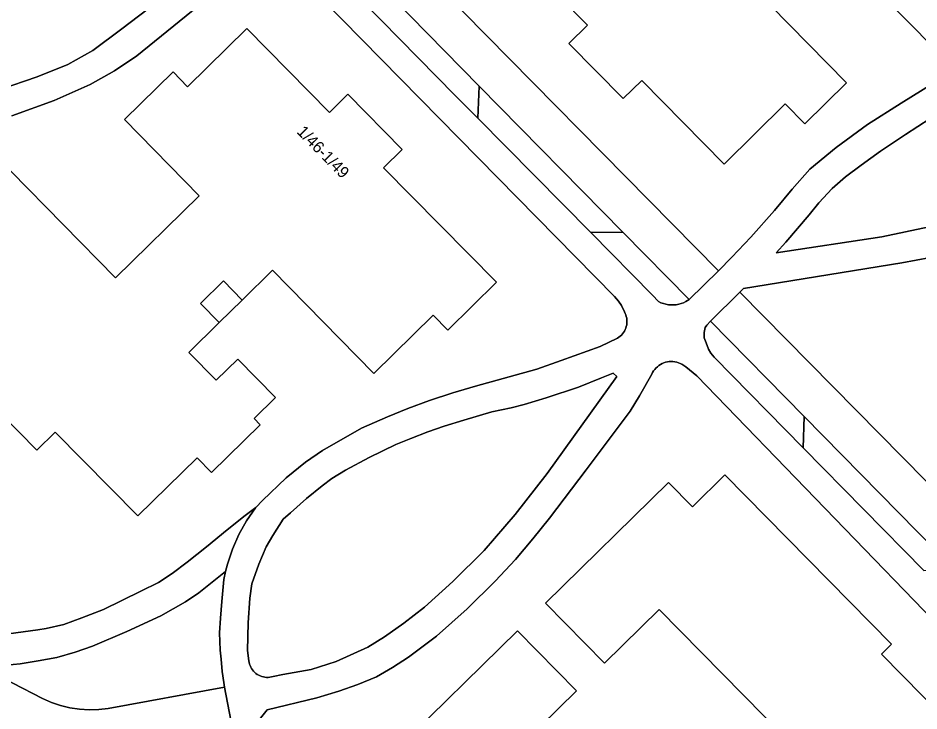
# Model space of a CAD drawing. Extents: x 162788 to 163838, y 385791 to 386523.
# Drawn here: x 162931.3 to 163008.9, y 386045.6 to 386105.3 of the extents above; entities that cross this region are included whole.
import ezdxf

# ---------------------------------------------------------------- set-up
doc = ezdxf.new("R2010")
doc.units = 0
for name, color, linetype in [('IMGEO_Berm_groen', 7, 'Continuous'), ('IMGEO_Erf', 7, 'Continuous'), ('IMGEO_Groenvoorziening', 7, 'Continuous'), ('IMGEO_Pand', 7, 'Continuous'), ('IMGEO_Pand_nummerreeks', 7, 'Continuous'), ('IMGEO_Pand_overbouw', 7, 'Continuous'), ('IMGEO_Parkeervlak_open', 7, 'Continuous'), ('IMGEO_Woonerf_gesloten', 7, 'Continuous'), ('IMGEO_Woonerf_open', 7, 'Continuous')]:
    doc.layers.add(name, color=color, linetype=linetype)

msp = doc.modelspace()

# ---------------------------------------------------------------- linework, layer by layer
at = {"layer": 'IMGEO_Berm_groen'}
for points in [[(162965.08, 386105.449), (162955.829, 386114.882), (162955.67, 386114.724), (162955.585, 386114.618), (162955.428, 386114.276), (162955.371, 386114.105), (162955.355, 386113.833), (162955.362, 386113.56), (162955.392, 386113.289), (162955.445, 386113.022), (162955.52, 386112.76), (162955.617, 386112.505), (162955.735, 386112.259), (162955.873, 386112.024), (162956.031, 386111.801), (162956.207, 386111.592), (162968.959, 386098.608), (162970.909, 386096.632), (162971.01, 386099.414)], [(162983.383, 386086.82), (162980.618, 386086.794), (162985.934, 386081.408), (162986.469, 386080.849), (162986.669, 386080.753), (162986.877, 386080.676), (162987.092, 386080.617), (162987.31, 386080.577), (162987.531, 386080.557), (162987.753, 386080.556), (162987.974, 386080.576), (162988.193, 386080.614), (162988.407, 386080.672), (162988.616, 386080.749), (162988.816, 386080.844), (162988.942, 386080.928), (162989.082, 386081.02)], [(162990.944, 386079.148), (162990.62, 386078.825), (162990.483, 386078.615), (162990.396, 386078.178), (162990.39, 386078.028), (162990.401, 386077.712), (162990.547, 386077.293), (162990.767, 386076.752), (162990.963, 386076.416), (162991.25, 386076.065), (162998.906, 386068.262), (162998.996, 386070.949)]]:
    msp.add_lwpolyline(points, close=True, dxfattribs=at)
at = {"layer": 'IMGEO_Erf'}
for points in [[(162996.056, 386106.378), (163002.631, 386099.689), (162999.051, 386096.17), (162997.375, 386097.874), (162992.098, 386092.687), (162985.007, 386099.902), (162983.413, 386098.336), (162978.742, 386103.088), (162980.335, 386104.654), (162970.65, 386114.508)], [(163015.416, 386107.909), (163010.138, 386102.721), (163001.39, 386111.622)], [(162926.041, 386051.625), (162933.013, 386052.569), (162933.742, 386052.696), (162935.247, 386053.046), (162936.802, 386053.624), (162938.661, 386054.329), (162941.895, 386055.895), (162943.405, 386056.649), (162944.576, 386057.437), (162945.884, 386058.394), (162947.555, 386059.728), (162949.331, 386061.183), (162950.86, 386062.423), (162951.804, 386063.106), (162952.362, 386063.711), (162954.399, 386065.67), (162956.061, 386067.017), (162957.518, 386068.011), (162960.88, 386069.936), (162963.125, 386070.93), (162964.884, 386071.639), (162966.754, 386072.319), (162968.761, 386072.976), (162970.713, 386073.558), (162975.991, 386075.021), (162978.07, 386075.777), (162981.439, 386076.986), (162982.931, 386077.699), (162983.051, 386077.779), (162983.163, 386077.868), (162983.267, 386077.967), (162983.362, 386078.074), (162983.448, 386078.189), (162983.524, 386078.31), (162983.589, 386078.438), (162983.643, 386078.571), (162983.685, 386078.708), (162983.716, 386078.848), (162983.734, 386078.99), (162983.74, 386079.133), (162983.734, 386079.276), (162983.716, 386079.419), (162983.686, 386079.559), (162983.644, 386079.696), (162983.59, 386079.829), (162983.525, 386079.956), (162983.265, 386080.523), (162983.02, 386080.87), (162982.66, 386081.282), (162954.193, 386110.271)], [(162965.639, 386109.891), (162991.633, 386083.508), (162992.764, 386084.687), (162994.399, 386086.394), (162996.434, 386088.681), (162997.975, 386090.519), (162999.497, 386092.25), (163001.748, 386094.127), (163004.452, 386096.104), (163007.355, 386097.946), (163010.914, 386100.137), (163014.526, 386102.37), (163018.012, 386104.467), (163019.81, 386105.476)], [(163034.593, 386105.372), (163032.927, 386102.387), (163031.643, 386100.544), (163030.645, 386099.338), (163027.569, 386096.044), (163022.475, 386091.076), (163020.687, 386089.641), (163019.2, 386088.539), (163019.01, 386088.395), (163017.057, 386087.161), (163014.761, 386086.098), (163012.296, 386085.312), (163009.878, 386084.654), (163007.401, 386084.184), (162993.768, 386081.986), (162993.461, 386081.653), (163039.475, 386034.95), (163041.516, 386037.028), (163076.704, 386072.029), (163076.476, 386072.907), (163056.429, 386093.317), (163049.21, 386100.56), (163041.713, 386107.825)], [(162947.311, 386106.699), (162941.55, 386102.006), (162939.629, 386100.72), (162937.541, 386099.543), (162934.439, 386098.157), (162930.777, 386096.853)], [(162930.69, 386092.088), (162939.722, 386082.898), (162946.911, 386089.964), (162940.472, 386096.515), (162944.659, 386100.63), (162945.913, 386099.353), (162951.013, 386104.365), (162958.121, 386097.133), (162959.715, 386098.699), (162964.386, 386093.946), (162962.793, 386092.38), (162972.495, 386082.509), (162968.309, 386078.394), (162967.054, 386079.671), (162961.955, 386074.659), (162953.224, 386083.541), (162950.621, 386080.983), (162948.997, 386082.635), (162947.014, 386080.687), (162948.638, 386079.034), (162948.614, 386079.011), (162946.035, 386076.475), (162948.385, 386074.084), (162950.23, 386075.897), (162953.491, 386072.58), (162951.647, 386070.766), (162952.172, 386070.232), (162947.986, 386066.117), (162946.731, 386067.393), (162941.632, 386062.381), (162934.523, 386069.614), (162932.93, 386068.048), (162928.259, 386072.8)], [(163011.849, 386051.6), (162989.767, 386074.455), (162988.809, 386075.231), (162988.47, 386075.446), (162988.326, 386075.52), (162988.176, 386075.581), (162988.022, 386075.628), (162987.864, 386075.662), (162987.703, 386075.682), (162987.541, 386075.687), (162987.38, 386075.678), (162987.22, 386075.655), (162987.062, 386075.618), (162986.909, 386075.568), (162986.76, 386075.504), (162986.618, 386075.427), (162986.483, 386075.338), (162986.356, 386075.237), (162986.239, 386075.126), (162986.132, 386075.005), (162986.035, 386074.875), (162985.951, 386074.736), (162985.88, 386074.591), (162984.829, 386072.717), (162984.021, 386071.401), (162980.229, 386066.357), (162977.078, 386062.205), (162975.634, 386060.423), (162974.149, 386058.622), (162972.405, 386056.76), (162969.989, 386054.397), (162967.345, 386052.021), (162964.947, 386050.227), (162963.558, 386049.32), (162962.181, 386048.538), (162960.58, 386047.87), (162958.929, 386047.281), (162957.046, 386046.716), (162952.772, 386045.677), (162952.201, 386044.966)], [(162997.379, 386043.276), (162986.518, 386054.326), (162981.811, 386049.699), (162976.729, 386054.87), (162987.312, 386065.272), (162989.376, 386063.173), (162992.179, 386065.928), (163006.528, 386051.329), (163005.665, 386050.481), (163011.004, 386045.049)], [(162963.728, 386042.091), (162974.311, 386052.493), (162979.393, 386047.323), (162974.686, 386042.696)]]:
    msp.add_lwpolyline(points, dxfattribs=at)
at = {"layer": 'IMGEO_Groenvoorziening'}
for points in [[(162929.787, 386099.112), (162932.958, 386100.213), (162935.592, 386101.258), (162937.761, 386102.46), (162940.24, 386104.343), (162943.236, 386106.606), (162946.028, 386108.902), (162949.063, 386111.524), (162950.921, 386113.462), (162948.954, 386115.694), (162947.799, 386116.794), (162946.824, 386117.743), (162946.592, 386117.975), (162939.45, 386114.029), (162938.78, 386111.247), (162928.686, 386105.678)], [(163009.853, 386096.622), (163007.712, 386095.24), (163005.571, 386093.816), (163003.901, 386092.61), (163002.561, 386091.584), (163001.4, 386090.589), (163000.259, 386089.362), (162999.427, 386088.32), (162997.429, 386085.958), (162996.591, 386085.049), (163005.677, 386086.422), (163009.76, 386087.281)], [(162928.277, 386049.302), (162933.436, 386046.663), (162934.194, 386046.325), (162934.979, 386046.056), (162935.786, 386045.858), (162936.606, 386045.733), (162937.435, 386045.682), (162938.265, 386045.705), (162939.089, 386045.802), (162949.104, 386047.652), (162949.031, 386048.049), (162948.89, 386048.985), (162948.796, 386050.058), (162948.72, 386050.827), (162948.671, 386052.304), (162948.757, 386053.581), (162948.852, 386055.03), (162949.026, 386056.922), (162949.185, 386057.594), (162946.884, 386055.763), (162945.735, 386054.981), (162943.62, 386053.772), (162940.69, 386052.427), (162937.717, 386051.164), (162936.23, 386050.641), (162934.657, 386050.182), (162933.055, 386049.899), (162931.506, 386049.649), (162929.659, 386049.476)]]:
    msp.add_lwpolyline(points, dxfattribs=at)
msp.add_lwpolyline([(162951.201, 386049.91), (162951.222, 386049.77), (162951.255, 386049.632), (162951.301, 386049.498), (162951.358, 386049.368), (162951.426, 386049.243), (162951.506, 386049.126), (162951.595, 386049.016), (162951.694, 386048.914), (162951.802, 386048.821), (162951.917, 386048.739), (162952.04, 386048.667), (162952.168, 386048.606), (162952.301, 386048.557), (162952.438, 386048.519), (162952.577, 386048.495), (162952.719, 386048.482), (162952.861, 386048.482), (162953.002, 386048.495), (162953.142, 386048.521), (162953.279, 386048.558), (162954.118, 386048.725), (162956.563, 386049.163), (162958.692, 386049.849), (162961.433, 386051.081), (162962.866, 386051.981), (162964.534, 386053.138), (162966.299, 386054.54), (162968.763, 386056.74), (162971.449, 386059.395), (162974.122, 386062.518), (162976.884, 386066.03), (162982.878, 386074.404), (162982.56, 386074.694), (162981.555, 386074.274), (162979.557, 386073.464), (162976.779, 386072.552), (162974.9, 386071.971), (162973.779, 386071.697), (162972.113, 386071.34), (162969.689, 386070.62), (162968, 386070.113), (162966.597, 386069.616), (162965.123, 386069.042), (162963.855, 386068.537), (162961.533, 386067.43), (162959.503, 386066.314), (162958.336, 386065.6), (162957.501, 386064.986), (162956.145, 386063.897), (162954.764, 386062.649), (162954.149, 386062.1), (162953.244, 386060.705), (162952.682, 386059.724), (162952.055, 386058.232), (162951.437, 386056.538), (162951.281, 386055.294), (162951.133, 386053.187), (162951.074, 386050.797)], close=True, dxfattribs=at)
at = {"layer": 'IMGEO_Pand'}
for points in [[(162970.65, 386114.508), (162980.335, 386104.654), (162978.742, 386103.088), (162983.413, 386098.336), (162985.007, 386099.902), (162992.098, 386092.687), (162997.375, 386097.874), (162999.051, 386096.17), (163002.631, 386099.689), (162996.056, 386106.378)], [(163001.39, 386111.622), (163010.138, 386102.721), (163015.416, 386107.909)], [(162928.259, 386072.8), (162932.93, 386068.048), (162934.523, 386069.614), (162941.632, 386062.381), (162946.731, 386067.393), (162947.986, 386066.117), (162952.172, 386070.232), (162951.647, 386070.766), (162953.491, 386072.58), (162950.23, 386075.897), (162948.385, 386074.084), (162946.035, 386076.475), (162948.614, 386079.011), (162948.638, 386079.034), (162947.014, 386080.687), (162948.997, 386082.635), (162950.621, 386080.983), (162953.224, 386083.541), (162961.955, 386074.659), (162967.054, 386079.671), (162968.309, 386078.394), (162972.495, 386082.509), (162962.793, 386092.38), (162964.386, 386093.946), (162959.715, 386098.699), (162958.121, 386097.133), (162951.013, 386104.365), (162945.913, 386099.353), (162944.659, 386100.63), (162940.472, 386096.515), (162946.911, 386089.964), (162939.722, 386082.898), (162930.69, 386092.088)], [(163011.004, 386045.049), (163005.665, 386050.481), (163006.528, 386051.329), (162992.179, 386065.928), (162989.376, 386063.173), (162987.312, 386065.272), (162976.729, 386054.87), (162981.811, 386049.699), (162986.518, 386054.326), (162997.379, 386043.276)], [(162974.686, 386042.696), (162979.393, 386047.323), (162974.311, 386052.493), (162963.728, 386042.091)]]:
    msp.add_lwpolyline(points, dxfattribs=at)
at = {"layer": 'IMGEO_Pand_overbouw'}
msp.add_lwpolyline([(162950.621, 386080.983), (162948.997, 386082.635), (162947.014, 386080.687), (162948.638, 386079.034)], close=True, dxfattribs=at)
at = {"layer": 'IMGEO_Parkeervlak_open'}
for points in [[(162971.01, 386099.414), (162970.909, 386096.632), (162980.618, 386086.794), (162983.383, 386086.82)], [(162998.996, 386070.949), (162998.906, 386068.262), (163009.288, 386057.681), (163011.984, 386057.726)]]:
    msp.add_lwpolyline(points, close=True, dxfattribs=at)
at = {"layer": 'IMGEO_Woonerf_gesloten'}
for points in [[(163010.914, 386100.137), (163007.355, 386097.946), (163004.452, 386096.104), (163001.748, 386094.127), (162999.497, 386092.25), (162997.975, 386090.519), (162996.434, 386088.681), (162994.399, 386086.394), (162992.764, 386084.687), (162991.633, 386083.508), (162989.082, 386081.02), (162988.942, 386080.928), (162988.816, 386080.844), (162988.616, 386080.749), (162988.407, 386080.672), (162988.193, 386080.614), (162987.974, 386080.576), (162987.753, 386080.556), (162987.531, 386080.557), (162987.31, 386080.577), (162987.092, 386080.617), (162986.877, 386080.676), (162986.669, 386080.753), (162986.469, 386080.849), (162985.934, 386081.408), (162980.618, 386086.794), (162970.909, 386096.632), (162968.959, 386098.608), (162956.207, 386111.592)], [(162954.193, 386110.271), (162982.66, 386081.282), (162983.02, 386080.87), (162983.265, 386080.523), (162983.525, 386079.956), (162983.59, 386079.829), (162983.644, 386079.696), (162983.686, 386079.559), (162983.716, 386079.419), (162983.734, 386079.276), (162983.74, 386079.133), (162983.734, 386078.99), (162983.716, 386078.848), (162983.685, 386078.708), (162983.643, 386078.571), (162983.589, 386078.438), (162983.524, 386078.31), (162983.448, 386078.189), (162983.362, 386078.074), (162983.267, 386077.967), (162983.163, 386077.868), (162983.051, 386077.779), (162982.931, 386077.699), (162981.439, 386076.986), (162978.07, 386075.777), (162975.991, 386075.021), (162970.713, 386073.558), (162968.761, 386072.976), (162966.754, 386072.319), (162964.884, 386071.639), (162963.125, 386070.93), (162960.88, 386069.936), (162957.518, 386068.011), (162956.061, 386067.017), (162954.399, 386065.67), (162952.362, 386063.711), (162951.804, 386063.106), (162951.775, 386063.074), (162950.999, 386061.958), (162950.331, 386060.774), (162949.776, 386059.533), (162949.34, 386058.245), (162949.185, 386057.594), (162949.026, 386056.922), (162948.852, 386055.03), (162948.757, 386053.581), (162948.671, 386052.304), (162948.72, 386050.827), (162948.796, 386050.058), (162948.89, 386048.985), (162949.031, 386048.049), (162949.104, 386047.652), (162949.631, 386044.804)], [(162943.236, 386106.606), (162940.24, 386104.343), (162937.761, 386102.46), (162935.592, 386101.258), (162932.958, 386100.213), (162929.787, 386099.112)], [(162930.777, 386096.853), (162934.439, 386098.157), (162937.541, 386099.543), (162939.629, 386100.72), (162941.55, 386102.006), (162947.311, 386106.699)], [(163009.76, 386087.281), (163005.677, 386086.422), (162996.591, 386085.049), (162997.429, 386085.958), (162999.427, 386088.32), (163000.259, 386089.362), (163001.4, 386090.589), (163002.561, 386091.584), (163003.901, 386092.61), (163005.571, 386093.816), (163007.712, 386095.24), (163009.853, 386096.622)], [(163009.288, 386057.681), (162998.906, 386068.262), (162991.25, 386076.065), (162990.963, 386076.416), (162990.767, 386076.752), (162990.547, 386077.293), (162990.401, 386077.712), (162990.39, 386078.028), (162990.396, 386078.178), (162990.483, 386078.615), (162990.62, 386078.825), (162990.944, 386079.148), (162993.461, 386081.653), (162993.768, 386081.986), (163007.401, 386084.184), (163009.878, 386084.654)], [(162952.201, 386044.966), (162952.772, 386045.677), (162957.046, 386046.716), (162958.929, 386047.281), (162960.58, 386047.87), (162962.181, 386048.538), (162963.558, 386049.32), (162964.947, 386050.227), (162967.345, 386052.021), (162969.989, 386054.397), (162972.405, 386056.76), (162974.149, 386058.622), (162975.634, 386060.423), (162977.078, 386062.205), (162980.229, 386066.357), (162984.021, 386071.401), (162984.829, 386072.717), (162985.88, 386074.591), (162985.951, 386074.736), (162986.035, 386074.875), (162986.132, 386075.005), (162986.239, 386075.126), (162986.356, 386075.237), (162986.483, 386075.338), (162986.618, 386075.427), (162986.76, 386075.504), (162986.909, 386075.568), (162987.062, 386075.618), (162987.22, 386075.655), (162987.38, 386075.678), (162987.541, 386075.687), (162987.703, 386075.682), (162987.864, 386075.662), (162988.022, 386075.628), (162988.176, 386075.581), (162988.326, 386075.52), (162988.47, 386075.446), (162988.809, 386075.231), (162989.767, 386074.455), (163011.849, 386051.6)]]:
    msp.add_lwpolyline(points, dxfattribs=at)
msp.add_lwpolyline([(162971.449, 386059.395), (162968.763, 386056.74), (162966.299, 386054.54), (162964.534, 386053.138), (162962.866, 386051.981), (162961.433, 386051.081), (162958.692, 386049.849), (162956.563, 386049.163), (162954.118, 386048.725), (162953.279, 386048.558), (162953.142, 386048.521), (162953.002, 386048.495), (162952.861, 386048.482), (162952.719, 386048.482), (162952.577, 386048.495), (162952.438, 386048.519), (162952.301, 386048.557), (162952.168, 386048.606), (162952.04, 386048.667), (162951.917, 386048.739), (162951.802, 386048.821), (162951.694, 386048.914), (162951.595, 386049.016), (162951.506, 386049.126), (162951.426, 386049.243), (162951.358, 386049.368), (162951.301, 386049.498), (162951.255, 386049.632), (162951.222, 386049.77), (162951.201, 386049.91), (162951.074, 386050.797), (162951.133, 386053.187), (162951.281, 386055.294), (162951.437, 386056.538), (162952.055, 386058.232), (162952.682, 386059.724), (162953.244, 386060.705), (162954.149, 386062.1), (162954.764, 386062.649), (162956.145, 386063.897), (162957.501, 386064.986), (162958.336, 386065.6), (162959.503, 386066.314), (162961.533, 386067.43), (162963.855, 386068.537), (162965.123, 386069.042), (162966.597, 386069.616), (162968, 386070.113), (162969.689, 386070.62), (162972.113, 386071.34), (162973.779, 386071.697), (162974.9, 386071.971), (162976.779, 386072.552), (162979.557, 386073.464), (162981.555, 386074.274), (162982.56, 386074.694), (162982.878, 386074.404), (162976.884, 386066.03), (162974.122, 386062.518)], close=True, dxfattribs=at)
at = {"layer": 'IMGEO_Woonerf_open'}
for points in [[(162965.639, 386109.891), (162958.387, 386117.423), (162955.829, 386114.882), (162965.08, 386105.449), (162971.01, 386099.414), (162983.383, 386086.82), (162989.082, 386081.02), (162991.633, 386083.508)], [(162993.461, 386081.653), (162990.944, 386079.148), (162998.996, 386070.949), (163011.984, 386057.726), (163020.157, 386049.405), (163033.251, 386036.073), (163036.859, 386032.401), (163039.227, 386034.698), (163039.475, 386034.95)]]:
    msp.add_lwpolyline(points, close=True, dxfattribs=at)
for points in [[(162929.659, 386049.476), (162931.506, 386049.649), (162933.055, 386049.899), (162934.657, 386050.182), (162936.23, 386050.641), (162937.717, 386051.164), (162940.69, 386052.427), (162943.62, 386053.772), (162945.735, 386054.981), (162946.884, 386055.763), (162949.185, 386057.594), (162949.34, 386058.245), (162949.776, 386059.533), (162950.331, 386060.774), (162950.999, 386061.958), (162951.775, 386063.074), (162951.804, 386063.106), (162950.86, 386062.423), (162949.331, 386061.183), (162947.555, 386059.728), (162945.884, 386058.394), (162944.576, 386057.437), (162943.405, 386056.649), (162941.895, 386055.895), (162938.661, 386054.329), (162936.802, 386053.624), (162935.247, 386053.046), (162933.742, 386052.696), (162933.013, 386052.569), (162926.041, 386051.625)], [(162930.686, 386030.397), (162936.107, 386035.521), (162932.694, 386038.826), (162936.924, 386043.047), (162938.012, 386042.989), (162938.953, 386043.053), (162939.857, 386043.208), (162947.781, 386044.732), (162940.49, 386037.455), (162941.913, 386036.079), (162949.845, 386043.684), (162949.631, 386044.804), (162949.104, 386047.652), (162939.089, 386045.802), (162938.265, 386045.705), (162937.435, 386045.682), (162936.606, 386045.733), (162935.786, 386045.858), (162934.979, 386046.056), (162934.194, 386046.325), (162933.436, 386046.663), (162928.277, 386049.302)]]:
    msp.add_lwpolyline(points, dxfattribs=at)

# ---------------------------------------------------------------- texts
at = {"layer": 'IMGEO_Pand_nummerreeks'}
msp.add_text('1/46-1/49', height=1, rotation=314.45558, dxfattribs=at).set_placement((162955.26, 386095.41))

doc.saveas('drawing.dxf')
